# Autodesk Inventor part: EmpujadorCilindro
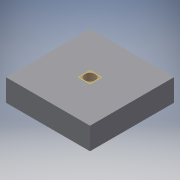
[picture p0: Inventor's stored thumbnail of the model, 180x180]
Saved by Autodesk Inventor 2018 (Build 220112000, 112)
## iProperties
Created: 2021-01
Part Number: EmpujadorCilindro
Material: Genérico
Document SubType Name: Modeling
Designer: ATOUZA
Density: 1 g/cm^3
Appearance: Valor por defecto
Author: ATOUZA
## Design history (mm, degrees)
node "Plano de trabajo1"
sketch "Boceto1"
  geometry: L1 (21.386, 19)-(-16.614, 19); L2 (-16.614, 19)-(-16.614, -19); L3 (-16.614, -19)-(21.386, -19); L4 (21.386, -19)-(21.386, 19); L5 (21.386, 19)-(-16.614, -19); L6 (-16.614, 19)-(21.386, -19); 2 further points
  constraints: 12 end point, 2 midpoint, 2 parallel, 1 horizontal, 1 perpendicular, 1 other
  dimensions: "d0" = 38 distance of L3.end L2.end; "d1" = 38 distance of L2.end L1.end
extrude "Extrusión1" new body sketch "Boceto1" distance "d2" = 10; taper "d3" = 0 deg
node "Sólido1"
node "Referencia1"
